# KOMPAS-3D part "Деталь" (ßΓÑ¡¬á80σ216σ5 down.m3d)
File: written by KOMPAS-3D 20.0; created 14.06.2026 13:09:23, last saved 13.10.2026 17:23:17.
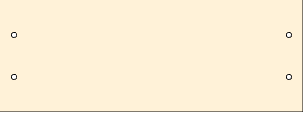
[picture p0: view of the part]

Document properties: Полное имя файла: D:\myProjects\Progect_esp32\box_compas\корпус\стенка80х216х5 down.m3d

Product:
- Part/product: Деталь
    Материал: Фанера, сосна,ФСФ ВВ/С  ГОСТ 3916.2-2018 (density 500 kg/m3)
    Масса: 0.0392075

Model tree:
1. Эскиз:3
2. Элемент выдавливания:4
     Расстояние 1 = 5
3. Эскиз:4  (with: Элемент выдавливания:4)
4. Элемент выдавливания:5
     Расстояние 2 = 216
5. Эскиз:5  (with: Элемент выдавливания:4)
6. Элемент выдавливания:6
     Расстояние 2 = 80
7. Эскиз:6  (with: Элемент выдавливания:4, Элемент выдавливания:6)
8. Элемент выдавливания:7
     Расстояние 2 = 5
9. Массив по сетке:1  (with: Элемент выдавливания:7, Эскиз:6)  (labels: Фанера, сосна,ФСФ ВВ/С  ГОСТ 3916.2-2018)  (4 pattern instances)
     Шаг 1 = 196; Угол раствора = -90; Шаг 2 = 30; Геометрический массив = 128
